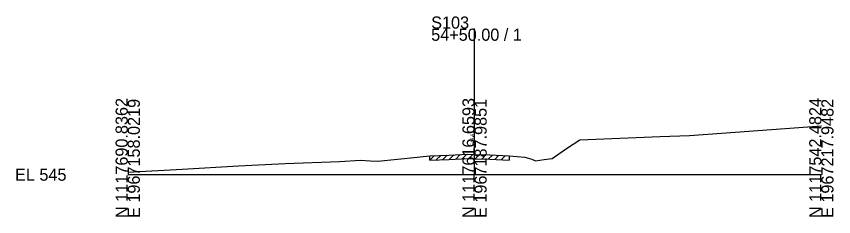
# Model space of a CAD drawing. Extents: x -26 to 163, y -10 to 45020.
# Drawn here: x -25.7 to 162.8, y 14490.3 to 14536.5 of the extents above; entities that cross this region are included whole.
import ezdxf

# ---------------------------------------------------------------- set-up
doc = ezdxf.new("R2010")
doc.units = 0
for name, color, linetype in [('RD_GPK_XS_Cell', 7, 'Continuous'), ('RD_XS_ExGround', 7, 'Continuous'), ('RD_XS_ExPaveRet', 7, 'Continuous'), ('RD_XS_TX_Elev_EX', 7, 'Continuous')]:
    doc.layers.add(name, color=color, linetype=linetype)

msp = doc.modelspace()

# ---------------------------------------------------------------- linework, layer by layer
at = {"layer": 'RD_GPK_XS_Cell'}
for p, q in [((80, 14500), (80, 14533.69)), ((0, 14500), (80, 14500)), ((80, 14500), (160, 14500))]:
    msp.add_line(p, q, dxfattribs=at)
at = {"layer": 'RD_XS_ExGround'}
for p, q in [((129.57, 14509.07), (136.95, 14509.58)), ((136.95, 14509.58), (160, 14511.23)), ((101.23, 14506.06), (104.29, 14508.03)), ((104.29, 14508.03), (122.85, 14508.79)), ((122.85, 14508.79), (129.57, 14509.07)), ((97.9, 14503.76), (101.23, 14506.06)), ((62.22, 14503.57), (66.79, 14504.02)), ((66.79, 14504.02), (68.18, 14504.17)), ((68.18, 14504.17), (69.67, 14504.33)), ((69.67, 14504.33), (74.05, 14504.53)), ((74.05, 14504.53), (78.48, 14504.73)), ((78.48, 14504.73), (80, 14504.67)), ((80, 14504.67), (83.51, 14504.54)), ((83.51, 14504.54), (87.99, 14504.37)), ((87.99, 14504.37), (89.83, 14504.2)), ((89.83, 14504.2), (91.63, 14504.01)), ((91.63, 14504.01), (93.23, 14503.58)), ((12.58, 14501.24), (25.56, 14502.06)), ((25.56, 14502.06), (36.29, 14502.55)), ((36.29, 14502.55), (48.82, 14503.01)), ((48.82, 14503.01), (53.73, 14503.35)), ((53.73, 14503.35), (55.89, 14503.2)), ((55.89, 14503.2), (57.73, 14503.08)), ((57.73, 14503.08), (62.22, 14503.57)), ((93.23, 14503.58), (94.09, 14503.21)), ((94.09, 14503.21), (96.08, 14503.5)), ((96.08, 14503.5), (97.9, 14503.76)), ((0, 14500.59), (12.58, 14501.24))]:
    msp.add_line(p, q, dxfattribs=at)
at = {"layer": 'RD_XS_ExPaveRet'}
for p, q in [((69.67, 14503.33), (70.72, 14504.38)), ((69.67, 14503.33), (69.67, 14504.33)), ((71.17, 14503.4), (72.22, 14504.45)), ((72.67, 14503.47), (73.72, 14504.51)), ((74.17, 14503.53), (75.22, 14504.58)), ((75.67, 14503.6), (76.72, 14504.65)), ((77.17, 14503.67), (78.22, 14504.72)), ((78.67, 14503.72), (79.63, 14504.68)), ((80.17, 14503.67), (81.13, 14504.63)), ((81.67, 14503.61), (82.63, 14504.57)), ((83.17, 14503.55), (84.13, 14504.52)), ((84.67, 14503.5), (85.63, 14504.46)), ((86.17, 14503.44), (87.13, 14504.4)), ((87.99, 14504.37), (87.99, 14503.37)), ((69.67, 14503.33), (74.05, 14503.53)), ((74.05, 14503.53), (78.48, 14503.73)), ((78.48, 14503.73), (80, 14503.67)), ((80, 14503.67), (83.51, 14503.54)), ((83.51, 14503.54), (87.99, 14503.37))]:
    msp.add_line(p, q, dxfattribs=at)

# ---------------------------------------------------------------- texts
at = {"layer": 'RD_GPK_XS_Cell'}
for s, p in [('S103', (70, 14533.69)), ('54+50.00 / 1', (70, 14530.89)), ('EL 545', (-26, 14498.6))]:
    msp.add_text(s, height=2.8, dxfattribs=at).set_placement(p)
for s, p in [('N 1117690.8362', (0, 14490)), ('E 1967158.0219', (2.8, 14490)), ('N 1117616.6593', (80, 14490)), ('E 1967187.9851', (82.8, 14490)), ('N 1117542.4824', (160, 14490)), ('E 1967217.9482', (162.8, 14490))]:
    msp.add_text(s, height=2.8, rotation=90, dxfattribs=at).set_placement(p)
at = {"layer": 'RD_XS_TX_Elev_EX'}
msp.add_text('549.67', height=0.8, rotation=90, dxfattribs=at).set_placement((79.9, 14506.67))

doc.saveas('drawing.dxf')
